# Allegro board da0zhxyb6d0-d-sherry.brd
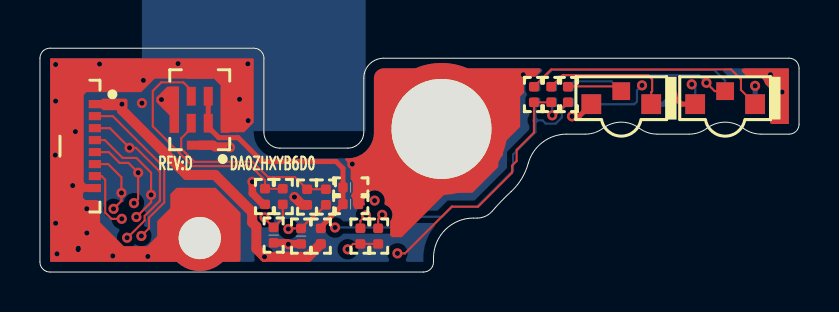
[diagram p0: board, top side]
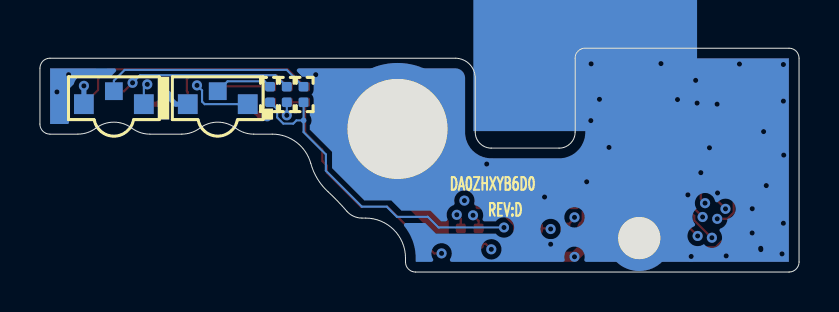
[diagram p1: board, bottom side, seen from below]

Outline 38 x 11.2 mm; copper layers: TOP, GND, IN1, IN2, VCC, BOTTOM. Coordinates in mm from the lower left corner of the outline.
Outline path: 0,10.7 arc(0.15,11.05) 0.5,11.2 10.71,11.2 arc(11.06,11.05) 11.21,10.7 11.21,7 arc(11.44,6.43) 12.01,6.2 15.41,6.2 arc(15.98,6.43) 16.21,7 16.21,9.7 arc(16.5,10.41) 17.21,10.7 37.5,10.7 arc(37.85,10.55) 38,10.2 38,7.4 arc(37.85,7.05) 37.5,6.9 36.1,6.9 arc(35.63,6.98) 35.2,7.2 arc(34.3,7.5) 33.4,7.2 arc(32.97,6.98) 32.5,6.9 30.9,6.9 arc(30.43,6.98) 30,7.2 arc(29.1,7.5) 28.2,7.2 arc(27.77,6.98) 27.3,6.9 26.37,6.9 arc(25.16,6.49) 24.44,5.43 arc(24.11,4.67) 23.58,4.02 arc(23.1,3.55) 22.64,3.05 arc(22.3,2.79) 21.88,2.7 21.7,2.7 arc(20.29,2.11) 19.7,0.7 19.7,0.5 arc(19.55,0.15) 19.2,0 0.5,0 arc(0.15,0.15) 0,0.5 0,10.7

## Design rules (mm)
constraint set DEFAULT: min track width 0.108

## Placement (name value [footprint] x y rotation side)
C136  0.1u/10v_4  [C0402]  15.56 4.24 0 top
C137  10u/6.3v_4  [C0402]  15.56 3.4 0 top
C864  *10p/50v_4  [C0402]  13.07 1.8 90 top
C865  *10p/50v_4  [C0402]  11.7 1.85 90 top
CN1  led_con  [50376-00801-V01-8P-L]  1.37 6.3 270 top
HOLE1  *h-c130d83p2  [H-C130D83P2]  8 1.7 0 top
HOLE2  *spad-zhx-1np  [SPAD-ZHX-1NP]  10.7 10.7 180 bottom
HOLE3  *h-c260d197p2  [H-C260D197P2]  20.1 7.16 0 top
L12  blm15pd121sn1d  [R0402]  14.06 1.8 90 top
LED1  led_red/blue  [LEDLTST-S326KGJRKT-3P-SMT]  34.3 8.4 0 bottom
LED2  led_amber/blue  [LEDLTST-S326KGJRKT-3P-SMT]  34.3 8.4 180 top
LED3  led_red/blue  [LEDLTST-S326KGJRKT-3P-SMT]  29.1 8.4 0 bottom
LED4  led_amber/blue  [LEDLTST-S326KGJRKT-3P-SMT]  29.1 8.4 180 top
NOREF  -  []  -33.77 -66.33 0 top
NOREF#2  -  []  17.03 -24.16 0 top
R1  51/f_4  [R0402]  24.8 8.88 90 bottom
R2  150/f_4  [R0402]  16.93 1.8 90 top
R3  150/f_4  [R0402]  25.64 8.88 90 bottom
R4  150/f_4  [R0402]  24.73 8.88 90 top
R1134  0_4  [R0402]  12.15 3.78 90 top
R1135  0_4  [R0402]  14.31 3.75 90 top
R1136  150/f_4  [R0402]  16.04 1.8 90 top
R1137  51/f_4  [R0402]  26.48 8.88 90 bottom
R1138  150/f_4  [R0402]  26.43 8.88 90 top
R1139  150/f_4  [R0402]  25.59 8.88 90 top
T9  *rclamp0531t  [R0402]  11.27 3.78 90 top
T10  *rclamp0531t  [R0402]  13.37 3.75 90 top
U2  spm0437hd4h-b  [MIC-KMM40301026-11DN-8P]  8 8.12 180 top

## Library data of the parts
C136 C137 C864 C865 = C0402
CN1 = 50376-00801-V01-8P-L
HOLE1 = H-C130D83P2
HOLE2 = SPAD-ZHX-1NP
HOLE3 = H-C260D197P2
L12 R1-R4 R1134-R1139 T9 T10 = R0402
LED1-LED4 = LEDLTST-S326KGJRKT-3P-SMT
U2 = MIC-KMM40301026-11DN-8P

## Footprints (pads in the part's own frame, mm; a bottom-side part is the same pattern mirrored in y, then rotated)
50376-00801-V01-8P-L
  rect 0.406x0.61 smd: 1(-2.1,1.375) 2(-1.5,1.375) 3(-0.9,1.375) 4(-0.3,1.375) 5(0.3,1.375) 6(0.9,1.375) 7(1.5,1.375) 8(2.1,1.375)
  rect 0.711x1.041 smd: 9(-3.05,0) 10(3.05,0)
C0402
  custom 0.12x0.12 smd: 1(0.39,0) 2(-0.39,0)
H-C130D83P2
  round 3.302 hole 2.108: 1(0,0)
H-C260D197P2
  round 6.604 hole 5.004: 1(0,0)
LEDLTST-S326KGJRKT-3P-SMT
  rect 0.991x0.991 smd: 1(-1.5,0) 3(1.5,0)
  rect 0.889x0.889 smd: 2(0,-0.65)
MIC-KMM40301026-11DN-8P
  rect 0.457x0.94 smd: 1(-0.425,0.675) 2(-0.425,-0.675) 3(0.425,-0.675) 4(0.425,0.675)
  rect 1.295x0.457 smd: 5(0,1.775) 7(0,-1.775)
  rect 0.457x2.311 smd: 6(-1.275,0) 8(1.275,0)
R0402
  custom 0.12x0.12 smd: 1(0.39,0) 2(-0.39,0)
SPAD-ZHX-1NP
  custom 1.825x1.825 smd: 1(0,0)

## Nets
+3V: CN1.1 L12.2 LED1.3 LED2.3 LED3.3 LED4.3
GND: C136.1 C137.1 C864.2 C865.2 CN1.8 CN1.9 CN1.10 HOLE1.1 HOLE2.1 HOLE3.1 T9.2 T10.2 U2.5 U2.6 U2.7 U2.8
VDD_3V3_MIC1: C136.2 C137.2 L12.1 U2.1 U2.2
DMIC_CLK: C865.1 CN1.7 R1134.2
DMIC_CLK_L: R1134.1 T9.1 U2.3
DMIC_DAT: C864.1 CN1.6 R1135.2
DMIC_DAT_L: R1135.1 T10.1 U2.4
EXT_LED_1: CN1.2 R1.2 R1137.2
EXT_LED_2: CN1.3 R3.2 R1138.2
EXT_LED_3: CN1.4 R4.2 R1139.2
EXT_LED_4: CN1.5 R2.2 R1136.2
N24138839: LED1.2 R1.1
N24138842: LED1.1 R2.1
N24138880: LED2.2 R3.1
N24138885: LED2.1 R4.1
N24143810: LED3.2 R1137.1
N24143812: LED3.1 R1136.1
N24143948: LED4.2 R1138.1
N24143950: LED4.1 R1139.1

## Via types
v1: diameter 0.508, hole 0.254, TOP to BOTTOM, 56 vias

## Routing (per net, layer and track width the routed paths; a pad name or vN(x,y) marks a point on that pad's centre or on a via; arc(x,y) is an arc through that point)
+3V: length 48.8
  TOP w0.254: LED4.3 26.99,7.79 v1(26.63,7.79) ; LED2.3 32.12,8.4 v1(31.66,8.86)
  TOP w0.508: L12.2 13.41,0.76 v1(11.24,0.76) 10.83,1.17 10.83,2.27 10.62,2.48 10.62,3 8.76,4.86 7.35,4.86 4.1,8.11 v1(4.1,8.4)
  VCC w0.254: v1(11.24,0.76) 13.51,0.76 14.39,1.64 18.38,1.64 19.44,2.71 19.95,2.71 20.59,3.35 21.89,3.35 23.58,5.04 23.58,5.89 24.84,7.14 24.84,7.88 25.41,8.45 25.97,8.45 v1(26.63,7.79) 27.06,7.79 27.55,8.27 31.08,8.27 v1(31.66,8.86) 35.34,8.86 v1(35.8,9.32)
  BOTTOM w0.254: LED3.3 31.21,8.4 v1(31.66,8.86) ; v1(35.8,9.32) LED1.3
GND: length 5.2
  TOP w0.381: v1(10.63,4.52) 10.63,3.94 11.18,3.39 T9.2 ; C864.2 12.45,1.41 v1(12.43,1.39) 12.37,1.46 C865.2
  TOP w0.457: U2.5 8.68,6.35 8.76,6.26 9.49,6.26 v1(9.51,6.24)
  TOP w0.483: v1(12.74,3.75) 13.13,3.36 T10.2
  vias: v1(0.78,10.38) v1(0.78,8.55) v1(0.77,5.85) v1(0.78,2.44) v1(0.85,0.91) v1(1.64,4.32) v1(1.77,7.03) v1(1.92,1.19) v1(1.91,1.12) v1(2.34,3.17) v1(2.35,1.95) v1(2.98,10.41) v1(3.65,0.81) v1(5.1,8.45) v1(5.18,9.59) v1(5.4,0.78) v1(6.08,8.63) v1(6.91,10.43) v1(9.99,8.64) v1(10.41,10.42) v1(10.42,7.58) v1(15.63,5.4) v1(24.19,9.87) v1(36.56,9.87) v1(37.15,9.01)
VDD_3V3_MIC1: length 12.6
  TOP w0.254: U2.2 U2.1 8.42,7.26 8.95,6.72 9.92,6.72 11.11,5.53 14.82,5.53 15.17,5.18 C136.2 C137.2 14.06,2.24 L12.1
DMIC_CLK: length 14.8
  TOP w0.108: v1(11.24,2.74) 11.24,2.68 11.69,2.24 C865.1 12.15,2.7 R1134.2 ; v1(4.1,2.66) 3.58,2.66 3.27,2.98 3.27,4.62 3.09,4.8 CN1.7
  IN1 w0.14: v1(4.1,2.66) 4.22,2.79 4.22,3.81 5.29,4.87 9.22,4.87 11.24,2.85 v1(11.24,2.74)
DMIC_CLK_L: length 12.4
  TOP w0.108: R1134.1 T9.1 11.27,4.59 10.56,5.3 7.64,5.3 7.2,5.74 7.2,5.74 6.97,5.96 6.97,5.97 5.65,7.29 5.65,9.07 6.08,9.49 7.18,9.49 7.57,9.1 U2.3
DMIC_DAT: length 17
  TOP w0.108: CN1.6 3.42,5.4 4.08,4.74 v1(4.08,3.96) 4.08,3.56 v1(3.68,3.16) ; v1(12.43,2.15) 12.47,2.19 C864.1 13.67,2.79 13.74,2.79 R1135.2
  IN1 w0.14: v1(3.68,3.16) 3.68,3.78 5.05,5.15 9.34,5.15 10.44,4.05 10.64,4.05 12.43,2.26 v1(12.43,2.15)
DMIC_DAT_L: length 9.6
  TOP w0.108: U2.4 7.57,7.2 7.08,6.7 7.08,6.17 7.19,6.06 7.19,6.05 7.28,5.96 7.29,5.96 7.73,5.52 10.65,5.52 11.42,4.74 12.77,4.74 T10.1 R1135.1
EXT_LED_1: length 41.9
  TOP w0.108: CN1.2 3.65,7.8 6.22,5.23 6.22,3.48 5.46,2.72 5.46,2.19 v1(5.08,1.81)
  IN1 w0.14: v1(14.77,2.23) 14.36,2.64 14.36,3.17 12.44,5.1 10.85,5.1 10.51,5.43 4.93,5.43 3.22,3.71 3.22,2.87 3.89,2.2 4.68,2.2 v1(5.08,1.81)
  BOTTOM w0.108: 24.8,7.59 25.16,7.59 25.32,7.43 25.81,7.43 26.12,7.74 26.12,8.14 R1137.2 ; 24.8,7.59 R1.2 ; 24.8,7.59 24.8,7 23.69,5.89 23.69,5.07 21.88,3.27 20.64,3.27 20.13,2.76 18.58,2.76 18.05,2.23 v1(14.77,2.23)
EXT_LED_2: length 39.9
  TOP w0.108: v1(4.36,1.72) 4.38,1.72 5.24,2.58 5.24,2.81 6,3.57 6,5.02 4.81,6.22 v1(4.48,6.22) 3.5,7.2 CN1.3 ; v1(25.64,7.84) 25.78,7.84 R1138.2
  IN1 w0.14: v1(16.75,3.58) 14.36,3.58 12.56,5.38 10.96,5.38 10.63,5.71 4.82,5.71 2.9,3.79 2.9,2.79 3.98,1.72 v1(4.36,1.72)
  IN2 w0.14: v1(25.64,7.84) 25.54,7.84 23.67,5.98 23.67,5.11 21.96,3.4 20.89,3.4 20.56,3.07 18.45,3.07 17.95,3.58 v1(16.75,3.58)
  BOTTOM w0.108: R3.2 v1(25.64,7.84)
EXT_LED_3: length 34
  TOP w0.108: v1(4.83,2.75) 5.56,3.49 v1(5.56,3.86) 5.56,4.97 4.83,5.71 4.14,5.71 3.25,6.6 CN1.4 ; R1139.2 R4.2 24.73,6.98 23.86,6.12 23.86,5.56 23.64,5.33 23.64,4.97 21.93,3.27 20.61,3.27 18.28,0.93 v1(17.9,0.93)
  IN1 w0.14: v1(4.83,2.75) 6.39,4.31 7.19,4.31 8.99,4.31 10.48,2.83 10.48,2.24 12.09,0.63 17.06,0.63 17.36,0.93 v1(17.9,0.93)
EXT_LED_4: length 19
  TOP w0.108: v1(4.71,3.45) 4.92,3.66 v1(4.92,4.97) 4.43,5.46 3.99,5.46 3.45,6 CN1.5 ; v1(15.41,1.14) 15.68,1.41 R1136.2 R2.2
  IN1 w0.14: v1(15.41,1.14) 14.67,1.14 14.44,0.91 12.21,0.91 10.76,2.36 10.76,2.94 9.11,4.59 5.85,4.59 v1(4.71,3.45)
N24138839: length 10.6
  BOTTOM w0.108: R1.1 25.65,10.12 33.76,10.12 34.3,9.57 LED1.2
N24138842: length 21
  TOP w0.108: v1(17.13,2.86) 16.93,2.66 R2.1
  IN1 w0.14: v1(32.63,9.39) 31.41,9.39 30.67,8.66 25.62,8.66 25.16,8.2 25.16,7.79 24.07,6.7 24.07,6.12 23.69,5.73 23.69,5.18 21.91,3.4 20.69,3.4 20.11,2.81 17.18,2.81 v1(17.13,2.86)
  BOTTOM w0.108: v1(32.63,9.39) 32.8,9.22 LED1.1
N24138880: length 9.2
  TOP w0.108: LED2.2 33.78,9.05 v1(33.36,9.47)
  BOTTOM w0.108: R3.1 26.22,9.85 32.98,9.85 v1(33.36,9.47)
N24138885: length 12.5
  TOP w0.108: LED2.1 35.09,9.11 35.09,9.65 34.6,10.14 25.59,10.14 R4.1
N24143810: length 2.9
  BOTTOM w0.108: R1137.1 26.75,9.54 28.61,9.54 LED3.2
N24143812: length 21.9
  TOP w0.108: R1136.1 16.04,2.56 v1(16.32,2.84)
  GND w0.127: v1(30.14,9.34) 29.3,8.5 25.53,8.5 24.96,7.93 24.96,7.13 23.66,5.84 23.66,5.1 23.1,4.54 23.1,4.41 21.98,3.3 20.49,3.3 19.6,2.41 16.75,2.41 v1(16.32,2.84)
  BOTTOM w0.108: v1(30.14,9.34) 29.88,9.09 29.88,8.53 29.76,8.4 LED3.1
N24143948: length 2.8
  TOP w0.108: R1138.1 26.45,9.29 28.86,9.29 LED4.2
N24143950: length 6.6
  TOP w0.108: LED4.1 30.6,9.01 30.65,9.05 30.65,9.65 30.44,9.85 26.17,9.85 R1139.1

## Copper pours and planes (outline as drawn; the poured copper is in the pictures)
+3V on TOP (solid shape): 4.38,8.6 4.38,8.22 4.26,8.1 3.16,8.1 3.05,8.2 2.44,8.2 2.44,8.6 3.05,8.6 3.13,8.68 4.31,8.68
GND on TOP (solid shape): 6.95,6.97 6.5,6.97 6.5,7.83 5.82,8.51 5.82,8.73 6.37,9.28 6.95,9.28
GND on TOP (solid shape): 37.49,7.41 36.61,7.41 36.55,7.47 36.55,9.18 36.3,9.43 35.99,9.79 35.52,9.74 35.43,9.74 35.16,10.02 35.13,10.13 35.23,10.19 37.49,10.19
GND on TOP (solid shape): 10.7,7.48 10.22,6.99 9.18,6.99 9.05,7.12 9.05,9.33 8.7,9.68 5.75,9.68 5.07,9 2.33,9 2.19,8.86 2.19,4.51 2.3,4.4 3.05,4.4 3.05,4.01 2.23,4.01 2.15,3.94 2.15,3.72 2.27,3.6 2.89,3.6 3.01,3.48 3.01,2.48 4.2,1.3 5.37,1.3 5.87,1.8 5.87,2.55 6.52,3.2 6.52,3.9 6.84,4.21 8.79,4.21 10.04,2.96 10.04,0.58 9.97,0.51 0.51,0.51 0.51,10.69 10.7,10.69
GND on TOP (solid shape): 24.96,10.19 25.06,10.13 25.04,10.02 24.79,9.77 24.58,9.77 24.33,9.66 24.22,9.41 24.22,9.13 24.23,9.06 24.25,8.99 24.04,8.78 24.04,7.26 23.17,6.4 23.17,5.84 22.95,5.61 22.95,5.26 21.65,3.96 20.33,3.96 18.11,1.74 17.62,1.74 17.53,1.83 17.53,2.54 17.62,3 17.31,3.34 17.26,3.39 17.25,3.46 17.16,3.88 16.79,4.08 16.36,3.89 16.27,3.43 16.27,3.38 16.25,3.34 16.13,3.31 16.01,3.24 16,3.23 15.94,3.23 15.93,3.24 15.82,3.28 15.71,3.3 15.68,3.31 15.66,3.35 15.66,3.55 15.64,3.67 15.58,3.78 15.57,3.78 15.56,3.82 15.57,3.85 15.58,3.86 15.64,3.96 15.66,4.09 15.66,4.39 15.63,4.53 15.55,4.65 15.55,5.34 15.29,5.61 15.28,5.66 15.32,5.69 15.41,5.69 16.33,6.08 16.72,7 16.72,9.7 16.86,10.05 17.21,10.19
GND on BOTTOM (solid shape): 37.49,7.41 36.59,7.41 36.55,7.45 36.55,9.16 36.3,9.41 36.01,9.78 35.54,9.75 34.48,9.75 34.22,10.02 34.19,10.13 34.29,10.19 37.49,10.19
GND on BOTTOM (solid shape): outline of 674 points within 0.51,0.51 25.14,10.69
GND on GND (solid shape): outline of 953 points within 0.51,0.51 37.49,10.69
GND on IN1 (solid shape): 10.7,7 10.8,6.51 11.07,6.09 11.09,5.98 11,5.92 4.57,5.92 2.67,4.02 2.58,3.93 2.58,2.66 3.84,1.39 3.97,1.39 4.37,1.21 4.76,1.4 5.52,1.55 5.27,2.28 5.2,2.35 5.22,2.44 5.31,2.6 5.34,2.78 5.34,2.8 5.94,3.4 8.86,3.4 10.94,1.32 10.97,1.24 10.93,1.17 10.76,0.93 10.75,0.64 10.73,0.55 10.65,0.51 0.51,0.51 0.51,10.69 10.7,10.69
GND on IN1 (solid shape): 14.04,3.04 14.04,2.5 14.26,2.28 14.26,2.25 15.13,1.87 14.75,2.74 14.72,2.74 14.69,2.77 14.69,3.25 15.8,3.25 15.88,3.2 15.88,3.1 16,2.44 16.67,2.47 16.74,2.5 16.81,2.47 17.14,2.36 17.48,2.49 19.71,2.49 19.8,2.43 19.79,2.32 19.35,1.56 19.19,0.7 19.19,0.51 18.41,0.51 18.32,0.56 18.33,0.66 18.19,1.35 17.5,1.26 16.74,1.26 16.44,0.95 16.01,0.95 15.93,0.99 15.91,1.07 15.61,1.6 15.01,1.46 14.54,1.46 14.31,1.23 12.34,1.23 11.42,2.15 11.42,2.25 11.46,2.27 11.51,2.3 11.56,2.34 11.61,2.4 11.69,2.44 11.76,2.41 11.93,2.24 11.93,2.21 11.93,2.14 11.93,2.07 11.95,2 12.23,1.69 12.66,1.7 12.8,1.8 12.9,1.95 12.86,2.43 12.45,2.66 12.43,2.66 10.83,4.26 10.56,4.26 10.39,4.43 10.39,4.76 10.5,4.88 12.2,4.88
GND on IN1 (solid shape): outline of 389 points within 12.84,3.14 37.49,10.19
GND on IN2 (solid shape): outline of 1011 points within 0.51,0.51 37.49,10.69
GND on VCC (solid shape): outline of 742 points within 0.51,0.51 37.49,10.69

Small or netless copper shapes (teardrops, artwork), in the pictures only: 1 on BOTTOM

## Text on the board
Ref Des/Silkscreen Bottom: REV:D | DA0ZHXYB6D0
Ref Des/Silkscreen Top: REV:D | DA0ZHXYB6D0
GND: GND | 2
VCC: VCC | 5
User.45: FIGURE | TYPE | Circle | SIZE | 10.0 | 83.0 | 197.0 | DRILL CHART: TOP to BOTTOM | ALL UNITS ARE IN MILS | PLATED | ROTATION | - | QTY | 49 | 1 | 51 | TOTAL HOLES:
